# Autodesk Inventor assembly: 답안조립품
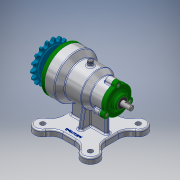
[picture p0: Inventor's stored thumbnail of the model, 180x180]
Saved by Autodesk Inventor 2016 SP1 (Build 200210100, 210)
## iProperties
Created: 2017-03
Part Number: 답안조립품
Document SubType Name: Assembly
Designer: Administrator
Author: Administrator
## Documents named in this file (14)
- D:\470307V1015\답안조립품.iam
- D:\470307V1015\본체.ipt
- D:\470307V1015\뒤커버.ipt
- D:\470307V1015\베어링-6200.ipt
- D:\470307V1015\베어링-6203.ipt
- D:\470307V1015\볼트 M4 x 12.ipt
- D:\470307V1015\볼트 M5 x 10.ipt
- 볼트 M5 x 10.ipt
- D:\470307V1015\스프로킷.ipt
- D:\470307V1015\앞커버.ipt
- D:\470307V1015\오일 실 10 20 7.ipt
- D:\470307V1015\오일 실 17 30 8.ipt
- D:\470307V1015\축.ipt
- D:\470307V1015\키5x5.ipt
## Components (15 placed, 1 different names)
1. ISO 4762 M4 x 12:1
2. ISO 4762 M4 x 12:3
3. ISO 4762 M4 x 12:4
4. ISO 4762 M4 x 12:2
5. ISO 4762 M4 x 12:5
6. ISO 4762 M4 x 12:6
7. ISO 4762 M4 x 12:7
8. ISO 4762 M4 x 12:8
9. ISO 4762 M4 x 12:9
10. ISO 4762 M4 x 12:10
11. ISO 4762 M4 x 12:11
12. ISO 4762 M4 x 12:12
13. ISO 4762 M4 x 12:13
14. ISO 4762 M4 x 12:14
15. ISO 4762 M4 x 12:15
